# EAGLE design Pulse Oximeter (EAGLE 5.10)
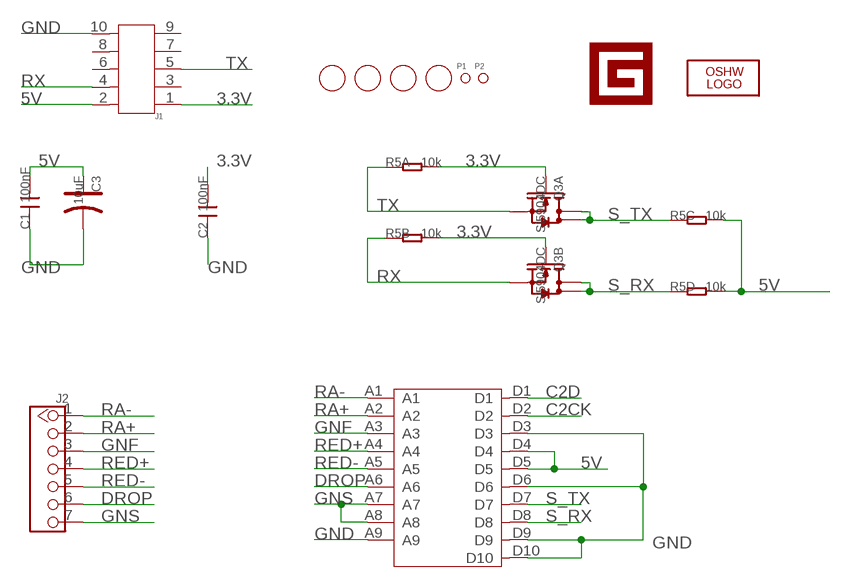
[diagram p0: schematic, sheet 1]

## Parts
C1  100nF  C-0603  [0603]
C2  100nF  C-0603  [0603]
C3  10uF  CAP-AVX-A  [AVX-A]
J1  HEADER-SHF-105-01-L-D-SM  [SHF-105-01-L-D-SM]
J2  TWIG-7P-2.0  [7P-2.0-90D]
LOGO1  LOGO-OSHW-FILLX0150-NT  [OSHW_FILLX150_NOTEXT]
P1  PAD-MARK  [ROUND-MARK-0.635]
P2  PAD-MARK  [ROUND-MARK-0.635]
Q3  Si5904DC  010-DUAL-N-MOSFET_1206-8  [1206-8]
R5  10k  005-4R_1206  [R1206-8]
U2  PULSE-OXIMETER  [PULSE-OXIMETER]
U$1  LOGO-GADGETEER-NORMAL  [GADGETEER-SILK]
U$2  PAD-HOLE'3.2/7.0'  [HOLE-3.2/7.0]
U$3  PAD-HOLE'3.2/7.0'  [HOLE-3.2/7.0]
U$4  PAD-HOLE'3.2/7.0'  [HOLE-3.2/7.0]
U$5  PAD-HOLE'3.2/7.0'  [HOLE-3.2/7.0]

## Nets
3.3V: C2.2 J1.1 Q3.2(A:G) Q3.4(B:G) R5.7 R5.8
5V: C1.2 C3.+ J1.2 R5.5 R5.6 U2.D4 U2.D5
C2CK: U2.D2
C2D: U2.D1
DROP: J2.6 U2.A6
GND: C1.1 C2.1 C3.- J1.10 U2.A9 U2.D3 U2.D6 U2.D9 U2.D10
GNF: J2.3 U2.A3
GNS: J2.7 U2.A7 U2.A8
RA+: J2.2 U2.A2
RA-: J2.1 U2.A1
RED+: J2.4 U2.A4
RED-: J2.5 U2.A5
RX: J1.4 Q3.3(B:S) R5.2
S_RX: Q3.5(B:D) Q3.6(B:D) R5.4 U2.D8
S_TX: Q3.7(A:D) Q3.8(A:D) R5.3 U2.D7
TX: J1.5 Q3.1(A:S) R5.1
Unconnected: J1.3 J1.6 J1.7 J1.8 J1.9

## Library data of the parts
C1 C2 = Discrete:C*: Ceramic Capacitors
C3 = Discrete:CAP*: Electrolytic Capacitors,Tantalum Capacitors and Super Capacitors
J1 = Connector:HEADER-SHF-105-01-L-D-SM
J2 = Connector:TWIG-7P-2.0
LOGO1 = Logo:LOGO-OSHW-FILL
P1 P2 = Discrete:PAD-MARK
Q3 = Discrete:010-DUAL-N-MOSFET*: Si5902BDC Si5904DC Si5908DC Si5920DC
R5 = Discrete:005-4R*: Resistor Array
U2 = Module:PULSE-OXIMETER
U$1 = Logo:LOGO-GADGETEER
U$2-U$5 = Discrete:PAD-HOLE

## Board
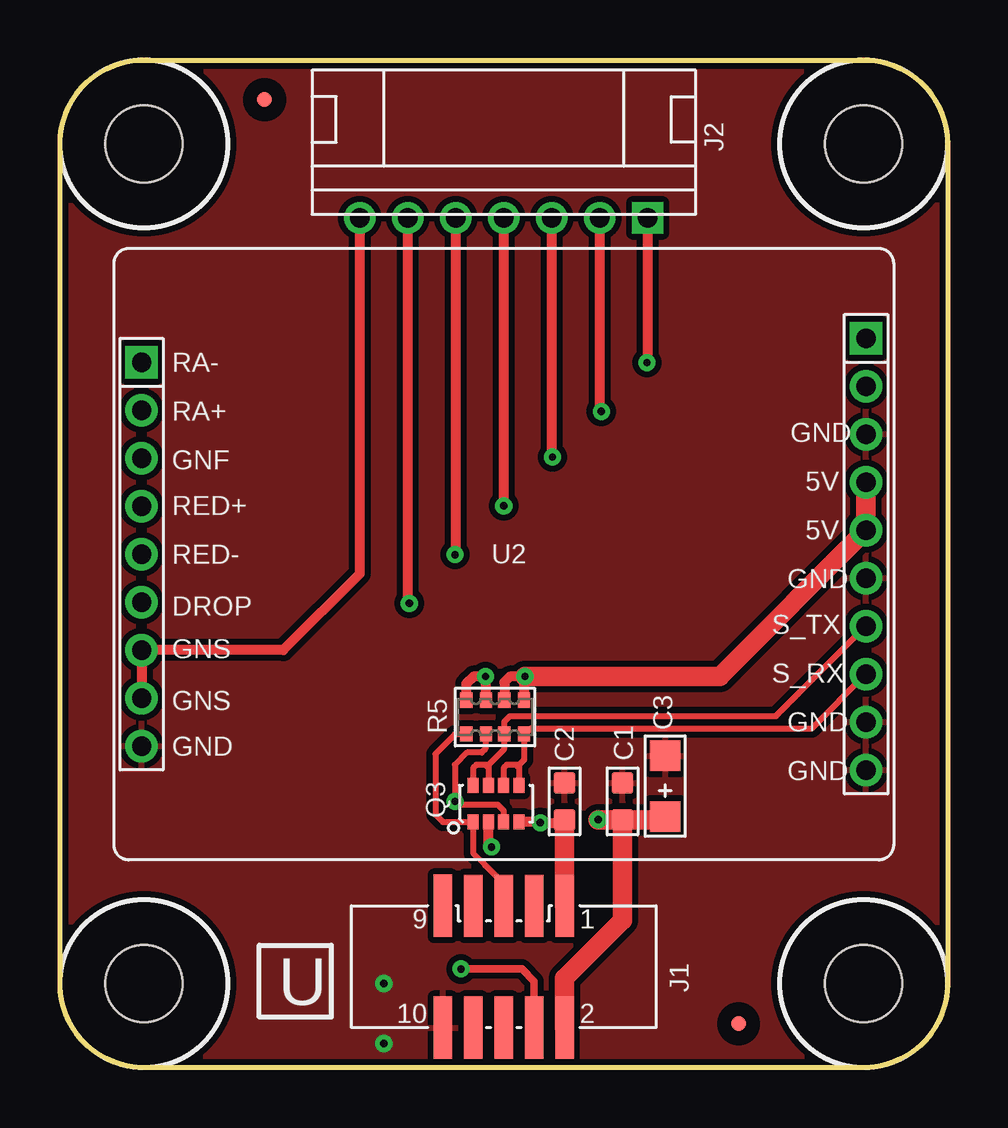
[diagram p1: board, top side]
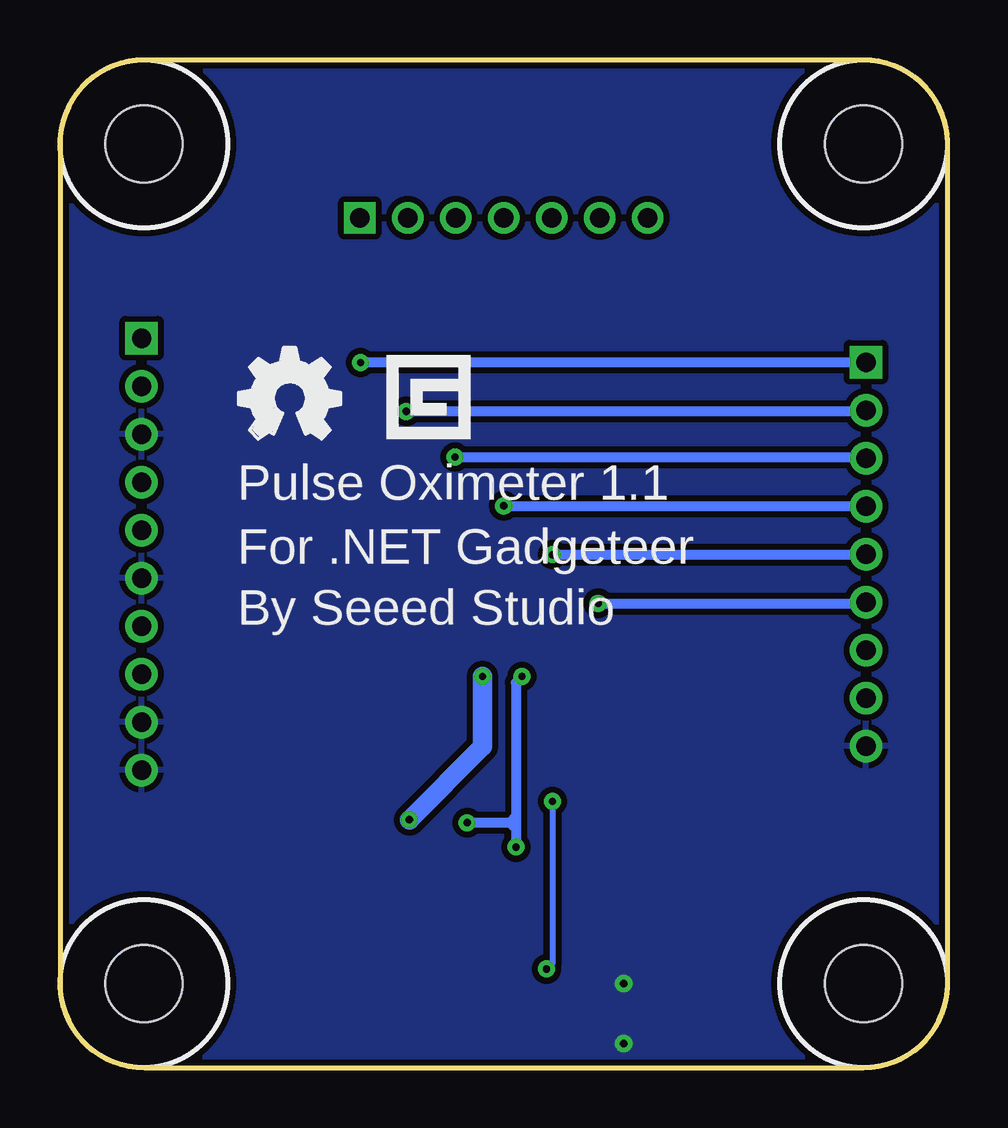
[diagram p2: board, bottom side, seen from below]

Size 37 x 42 mm. Coordinates in mm from the lower left corner, seen from the top.
Outline: 33.5,42 arc-90 37,38.5 37,3.5 arc-90 33.5,0 3.5,0 arc-90 0,3.5 0,38.5 arc-90 3.5,42 33.5,42
Copper layers (1*16): Top 0.035mm / dielectric 1.5mm / Bottom 0.035mm
Design rules "default *": minimum track width 10mil, minimum drill 12mil, track to track 8mil, track to pad 8mil, pad to pad 8mil, via to via 8mil, smd to smd 8mil, copper to edge 10mil, drill to drill 8mil, minimum pad ring 10mil, minimum via ring 8mil, stop-mask expansion 4mil, vias tented up to drill 100mil, thermal gap 10mil

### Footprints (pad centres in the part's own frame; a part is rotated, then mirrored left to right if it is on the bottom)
0603 = smd 0.889 x 0.889: 1 -0.762,0; 2 0.762,0
AVX-A = smd 1.27 x 1.27: + -1.27,0; - 1.27,0
SHF-105-01-L-D-SM = smd 0.762 x 2.6: 1 -2.54,-2.54; 2 -2.54,2.54; 3 -1.27,-2.54; 4 -1.27,2.54; 5 0,-2.54; 6 0,2.54; 7 1.27,-2.54; 8 1.27,2.54; 9 2.54,-2.546; 10 2.54,2.54
7P-2.0-90D = drill 0.8 pad 1.3 square: 1 -6,3.15 | drill 0.8 pad 1.3 round: 2 -4,3.15; 3 -2,3.15; 4 0,3.15; 5 2,3.15; 6 4,3.15; 7 6,3.15
ROUND-MARK-0.635 = smd 0.635 x 0.635: P$1 0,0
1206-8 = smd 0.457 x 0.635: 1 -0.953,-0.762; 2 -0.318,-0.762; 3 0.318,-0.762; 4 0.953,-0.762; 5 0.953,0.762; 6 0.318,0.762; 7 -0.318,0.762; 8 -0.953,0.762
R1206-8 = smd 0.508 x 0.635: 1 -1.206,-0.699; 2 -0.381,-0.699; 3 0.381,-0.699; 4 1.206,-0.699; 5 1.206,0.699; 6 0.381,0.699; 7 -0.381,0.699; 8 -1.206,0.699
PULSE-OXIMETER = drill 0.8 pad 1.35 square: A1 -15.1,8; D1 15.1,9 | drill 0.8 pad 1.35 round: A2 -15.1,6; A3 -15.1,4; A4 -15.1,2; A5 -15.1,0; A6 -15.1,-2; A7 -15.1,-4; A8 -15.1,-6; A9 -15.1,-8; D2 15.1,7; D3 15.1,5; D4 15.1,3; D5 15.1,1; D6 15.1,-1; D7 15.1,-3; D8 15.1,-5; D9 15.1,-7; D10 15.1,-9
HOLE-3.2/7.0 = hole 3.2: 0,0

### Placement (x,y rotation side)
C1  23.45,11.09 270 top
C2  21.04,11.09 270 top
C3  25.23,11.73 90 top
J1  18.5,4.2 180 top
J2  18.5,38.57 180 top
LOGO1  29.55,26.21 0 bottom
P1  28.3,1.82 0 top
P2  8.53,40.35 0 top
Q3  18.18,11 0 top
R5  18.14,14.61 0 top
U2  18.5,21.4 0 top
U$1  21.22,28.38 0 bottom
U$2  3.5,38.5 0 top
U$3  3.5,3.5 0 top
U$4  33.5,3.5 0 top
U$5  33.5,38.5 0 top

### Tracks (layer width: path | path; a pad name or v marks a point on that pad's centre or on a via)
3.3V  (via drill 0.3 pad 0.64)
  Top 0.406: Q3.2 17.86,9.32 v17.99,9.19 | C2.2 20.91,10.21 v20.02,10.21 19.99,10.24 Q3.4 | R5.7 17.74,15.33 v17.74,16.3 17.23,16.3 16.93,16 R5.8
  Top 0.813: C2.2 J1.1
  Bottom 0.406: 17.99,10.46 17.99,9.95 | 17.99,9.95 v17.99,9.19 | 18.25,10.21 18.12,10.21 | 17.99,10.46 18.25,10.21 | 18.25,10.21 v20.02,10.21 | 17.99,9.95 18.25,10.21 | 17.99,10.46 17.99,16.05 v17.74,16.3
5V  (via drill 0.3 pad 0.64)
  Top 0.406: R5.6 18.52,16.07 18.75,16.3 v19.39,16.3 19.35,16.26 R5.5
  Top 0.813: v22.44,10.33 C1.2 | C1.2 25.1,10.33 C3.+ | C1.2 23.45,6.14 21.04,3.73 J1.2 | v19.39,16.3 27.5,16.3 U2.D5 U2.D4
  Bottom 0.813: v19.39,16.3 19.39,13.38 v22.44,10.33
DROP  (via drill 0.3 pad 0.64)
  Top 0.406: J2.6 14.5,19.41 v14.56,19.35
  Bottom 0.406: v14.56,19.35 3.45,19.35 U2.A6
GND  (via drill 0.3 pad 0.64)
  other vias: 13.5,3.5 13.5,1
  pour Top (isolate 0.254): -0.55,42.59 38.19,42.59 38.19,-0.59 -0.55,-0.59
  pour Bottom (isolate 0.254): -0.55,42.59 38.19,42.59 38.19,-0.59 -0.55,-0.59
GNF  (via drill 0.3 pad 0.64)
  Top 0.406: J2.3 20.5,25.48 v20.53,25.45
  Bottom 0.406: v20.53,25.45 3.45,25.45 U2.A3
GNS
  Top 0.406: J2.7 12.5,20.59 9.31,17.4 U2.A7 U2.A8
RA+  (via drill 0.3 pad 0.64)
  Top 0.406: J2.2 22.5,27.41 v22.56,27.35
  Bottom 0.406: v22.56,27.35 3.45,27.35 U2.A2
RA-  (via drill 0.3 pad 0.64)
  Top 0.406: J2.1 24.5,29.41 v24.47,29.38
  Bottom 0.406: v24.47,29.38 3.42,29.38 U2.A1
RED+  (via drill 0.3 pad 0.64)
  Top 0.406: v18.5,23.41 J2.4
  Bottom 0.406: v18.5,23.41 3.41,23.41 U2.A4
RED-  (via drill 0.3 pad 0.64)
  Top 0.406: J2.5 16.5,21.41 v16.47,21.38
  Bottom 0.406: v16.47,21.38 3.42,21.38 U2.A5
RX  (via drill 0.3 pad 0.64)
  Top 0.254: Q3.3 18.5,10.72 18.25,10.97 16.59,10.97 v16.47,11.09 16.47,12.62 16.98,13.13 17.58,13.13 17.74,13.28 17.74,13.89 R5.2
  Top 0.305: J1.4 19.77,3.6 19.26,4.11 v16.72,4.11
  Bottom 0.254: v16.47,11.09 16.47,4.36 v16.72,4.11
S_RX
  Top 0.254: 19.14,12.62 19.35,12.83 R5.4 19.41,13.91 19.64,14.14 31.34,14.14 U2.D8 | 19.14,12.62 19.14,12.49 | 19.14,12.49 Q3.5 | Q3.6 18.5,12.49 18.63,12.62 19.01,12.62 | 19.14,12.62 19.01,12.62 | 19.14,12.49 19.01,12.62
S_TX
  Top 0.254: U2.D7 29.85,14.65 18.75,14.65 18.52,14.42 R5.3 18.5,13.89 18.5,13.25 17.86,12.62 | Q3.8 17.23,12.49 17.36,12.62 17.74,12.62 | 17.74,12.62 17.86,12.62 | 17.86,12.62 Q3.7 | 17.74,12.62 17.86,12.49
TX
  Top 0.254: R5.1 16.91,13.89 16.47,13.89 15.65,13.07 15.65,10.55 15.96,10.24 Q3.1 17.23,8.94 17.74,8.43 18.5,7.66 J1.5

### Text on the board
tPlace: RA- | RA+ | GND | GNF | 5V | RED+ | 5V | RED- | GND | DROP | S_TX | GNS | S_RX | GNS | GND | GND | GND | U
bPlace: Pulse Oximeter 1.1 | For .NET Gadgeteer | By Seeed Studio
